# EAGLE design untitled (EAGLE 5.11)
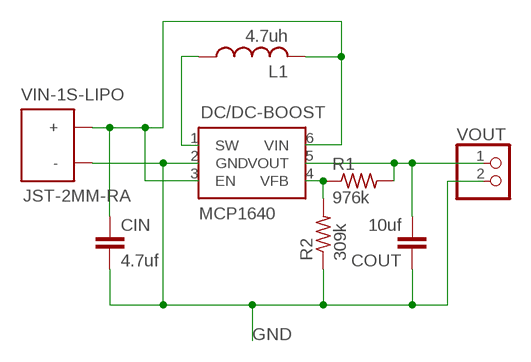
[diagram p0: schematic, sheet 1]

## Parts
CIN  4.7uf  C-EUC0805  [C0805]
COUT  10uf  C-EUC0805  [C0805]
DC/DC-BOOST  MCP1640  [SOT-23-6]
L1  4.7uh  L-USL3216C  [L3216C]
R1  976k  R-US_R0805  [R0805]
R2  309k  R-US_R0805  [R0805]
VIN-1S-LIPO  JST-2MM-RA  JST-2MM-BAT-RIGHT-ANGLE  [JST-2MM-BAT-RIGHT-ANGLE]
VOUT  PINHD-1X2  [1X02]

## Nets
GND: CIN.2 COUT.1 DC/DC-BOOST.2(GND) R2.1 VIN-1S-LIPO.2(-) VOUT.2
N$1: CIN.1 DC/DC-BOOST.3(EN) DC/DC-BOOST.6(VIN) L1.2 VIN-1S-LIPO.1(+)
N$2: COUT.2 DC/DC-BOOST.5(VOUT) R1.2 VOUT.1
N$3: DC/DC-BOOST.1(SW) L1.1
N$4: DC/DC-BOOST.4(VFB) R1.1 R2.2

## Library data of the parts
CIN COUT = rcl:C-EU: CAPACITOR, European symbol
DC/DC-BOOST = trl:MCP1640
L1 = rcl:L-US: INDUCTOR, American symbol
R1 R2 = resistor:R-US_: RESISTOR, American symbol
VIN-1S-LIPO = trl:JST-2MM-BAT-RIGHT-ANGLE
VOUT = pinhead:PINHD-1X2: PIN HEADER

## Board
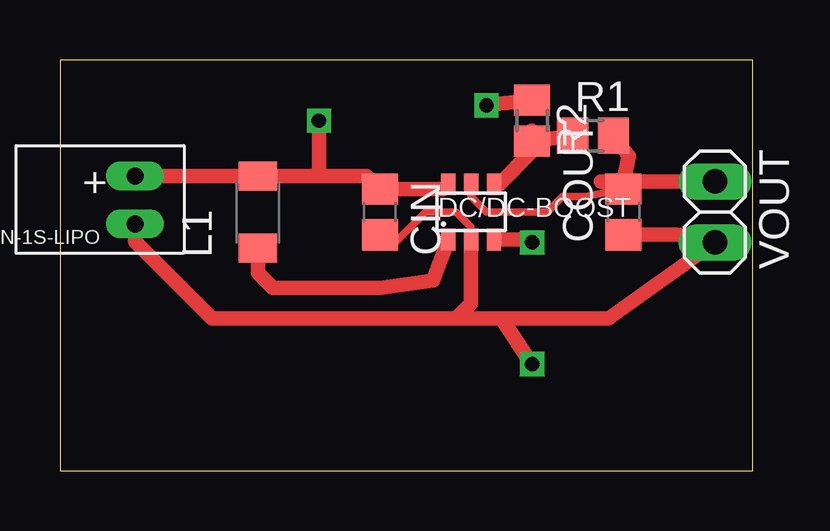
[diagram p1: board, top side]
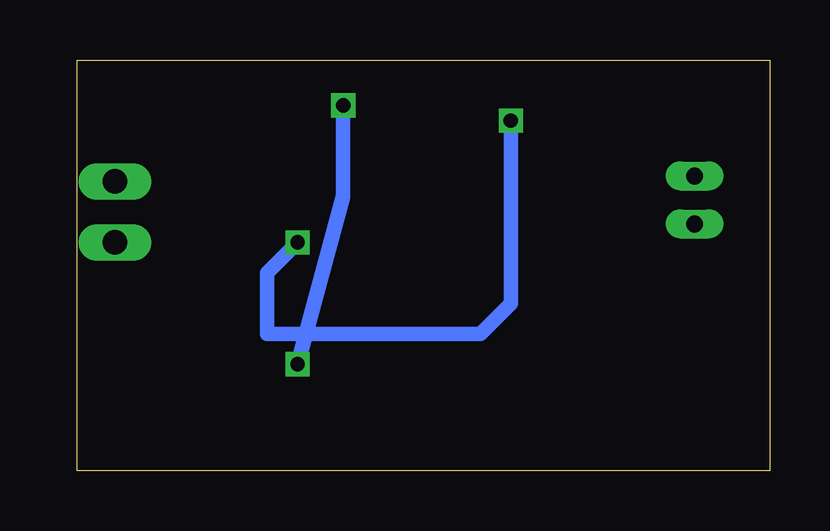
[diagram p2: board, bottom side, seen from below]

Size 28.88 x 17.14 mm. Coordinates in mm from the lower left corner, seen from the top.
Outline: 0,0 28.88,0 28.88,17.14 0,17.14 0,0
Copper layers (1*16): Top 0.035mm / dielectric 1.5mm / Bottom 0.035mm
Design rules "default": minimum track width 10mil, minimum drill 24mil, track to track 8mil, track to pad 8mil, pad to pad 8mil, via to via 8mil, smd to smd 8mil, copper to edge 40mil, drill to drill 8mil, minimum pad ring 10mil, minimum via ring 8mil, stop-mask expansion 4mil, vias tented up to drill 0mil, thermal gap 10mil

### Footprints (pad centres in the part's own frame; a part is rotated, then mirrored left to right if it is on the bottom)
C0805 = smd 1.3 x 1.5: 1 -0.95,0; 2 0.95,0
SOT-23-6 = smd 0.6 x 0.9: 1 -0.95,-1.15; 2 0,-1.15; 3 0.95,-1.15; 4 0.95,1.15; 5 0,1.15; 6 -0.95,1.15
L3216C = smd 1.2 x 1.6: 1 -1.5,0; 2 1.5,0
R0805 = smd 1.3 x 1.5: 1 -0.85,0; 2 0.85,0
JST-2MM-BAT-RIGHT-ANGLE = drill 0.7 pad 1.016 long: 1 -2.5,-1.5; 2 -2.5,0.5
1X02 = drill 1.016 long: 1 -1.27,0; 2 1.27,0

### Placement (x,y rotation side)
CIN  13.34,10.79 270 top
COUT  23.5,10.79 90 top
DC/DC-BOOST  17.14,10.79 0 top
L1  8.26,10.79 90 top
R1  22.23,13.97 0 top
R2  19.68,14.61 270 top
VIN-1S-LIPO  0.64,10.79 180 top
VOUT  27.3,10.79 270 top

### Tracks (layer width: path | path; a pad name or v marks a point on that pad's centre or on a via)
GND  (via drill 0.6)
  Top 0.305: DC/DC-BOOST.2 17.14,10.16 16.51,10.79 15.24,10.79 13.97,9.53 13.65,9.53 CIN.2
  Top 0.61: VIN-1S-LIPO.2 3.13,9.56 6.35,6.35 16.51,6.35 | 16.51,6.35 17.14,6.99 DC/DC-BOOST.2 | 16.51,6.35 18.41,6.35 | 18.41,6.35 22.86,6.35 VOUT.2 25.71,9.85 COUT.1 | v17.78,15.24 R2.1 | 18.41,6.35 v19.68,4.45
  Bottom 0.61: v17.78,15.24 17.78,11.43 v19.68,4.45
N$1  (via drill 0.6)
  Top 0.61: VIN-1S-LIPO.1 L1.2 10.79,12.29 | 10.79,12.29 12.79,12.29 CIN.1 15.99,11.74 DC/DC-BOOST.6 | DC/DC-BOOST.3 19.57,9.64 v19.68,9.53 | 10.79,12.29 v10.79,14.61
  Bottom 0.61: v19.68,9.53 20.95,8.26 20.95,5.71 12.06,5.71 10.79,6.99 v10.79,14.61
N$2
  Top 0.305: DC/DC-BOOST.5 17.14,11.43 17.78,10.79 20.32,10.79 20.95,11.43 21.91,11.43 COUT.2
  Top 0.61: 23.5,12.06 22.55,12.06 COUT.2 | 23.5,12.06 VOUT.1 | R1.2 23.71,13.12 23.5,12.06
N$3
  Top 0.61: DC/DC-BOOST.1 15.56,7.94 13.34,7.62 8.89,7.62 8.26,8.26 L1.1
N$4
  Top 0.61: R1.1 R2.2 19.68,14.19 19.68,13.34 18.3,11.95 DC/DC-BOOST.4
